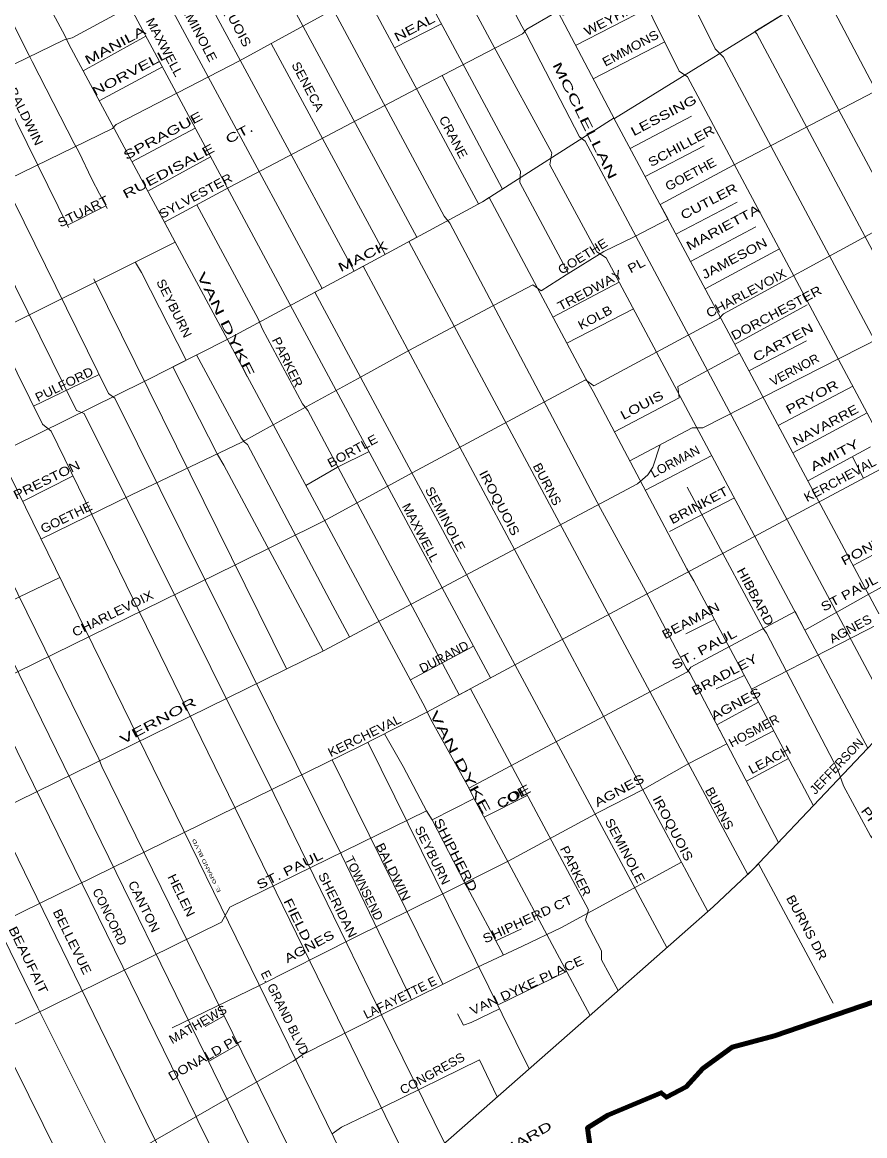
# Model space of a CAD drawing. Extents: x 34705 to 138605, y 34275 to 143551.
# Drawn here: x 109243 to 116315, y 106218 to 115565 of the extents above; entities that cross this region are included whole.
import ezdxf
from ezdxf.enums import TextEntityAlignment as Align

# ---------------------------------------------------------------- set-up
doc = ezdxf.new("R2010")
doc.units = 0
doc.header["$LTSCALE"] = 30
for name, color, linetype, lineweight in [('1', 7, 'Continuous', 13), ('11', 7, 'Continuous', 13), ('3', 7, 'Continuous', 13), ('58', 7, 'Continuous', 106)]:
    doc.layers.add(name, color=color, linetype=linetype, lineweight=lineweight)

msp = doc.modelspace()

# ---------------------------------------------------------------- linework, layer by layer
at = {"layer": '1'}
for p, q in [((113886.78, 115371.05), (114496.41, 115682.06)), ((112367.5, 115350.01), (112760.69, 115552.45)), ((109752.78, 115158.44), (110281.24, 115447.03)), ((111331.39, 115387.68), (112288.76, 113616.18)), ((114035.18, 115090.07), (114636.51, 115399.94)), ((109888.37, 114906.05), (110419.43, 115189.78)), ((112768.64, 115118.2), (113273.77, 114165.05)), ((114345.6, 114506.33), (114860.25, 114775.18)), ((110163.35, 114394.23), (110694.85, 114677.04)), ((114471.31, 114271.08), (114967.12, 114527.61)), ((110295.53, 114148.19), (110823.89, 114435.94)), ((114729.93, 113787.1), (115242.73, 114054.99)), ((109622.03, 113861.42), (109944.08, 114024.34)), ((114853.32, 113556.17), (115400.22, 113846.81)), ((114976.35, 113325.95), (115599.28, 113662.78)), ((109844, 113412.08), (111462.04, 110136.55)), ((113696.77, 113090.42), (114254.23, 113383.62)), ((113814.34, 112869.61), (114374.34, 113158.54)), ((115227.64, 112861.31), (115832.85, 113193.12)), ((109337.82, 112341.44), (109888.87, 112607.97)), ((115588.54, 112180.29), (116213.95, 112510.8)), ((115716.46, 111953.21), (116334.36, 112285.15)), ((115836.78, 111715.73), (116362.4, 111999.78)), ((114473.5, 111636.06), (115031.56, 111927.06)), ((116211.01, 111917.96), (116305.48, 111736.85)), ((109244.17, 111542.82), (109669.91, 111756.41)), ((114674.81, 111289.59), (115221.21, 111571.7)), ((114813.85, 110430.13), (115052.58, 110552.45)), ((112500.57, 110043.86), (113031.45, 110327.09)), ((115066.96, 109968.76), (115303.94, 110081.36)), ((115550.43, 109617.74), (115314.93, 109493.76)), ((112144.23, 109520.93), (113497.34, 106777.82)), ((111843.37, 109372.24), (112774.54, 107490.01)), ((115673.8, 109385.27), (115321.55, 109194.16)), ((113482.27, 109074.12), (113119.43, 108892.64)), ((113119.43, 108892.64), (113482.27, 109074.12)), ((113232.85, 107314), (113812.1, 107597.42)), ((110777.33, 107133.27), (110936.56, 107225.16)), ((110806.19, 106842.08), (111055.76, 106982.12))]:
    msp.add_line(p, q, dxfattribs=at)
for points in [[(109066.8, 125332.04), (109139.19, 124140.51), (109193.78, 124144.98), (109227.01, 123732.2), (109292.24, 123739.86), (109299.93, 123624.73), (109369.7, 123008.18), (109372.73, 122982.47), (109448.74, 123000.85), (109451.11, 122990.73), (109683.7, 122092.08), (109694.5, 122052.82), (109774.89, 122075.33), (109805.8, 122057.18), (110288.42, 121714), (110509.38, 121562.77), (110526.82, 121556.95), (110678.01, 121446.44), (110741.97, 121388.27), (113721.98, 115682.24), (113768.5, 115595), (114188.6, 114799.58), (114229.3, 114723.97), (116785.76, 109939.79)], [(111500.38, 122480.84), (111640.33, 122189.5), (111675.22, 122113.89), (112175.28, 121094.54), (112529.97, 120408.19), (113442.88, 118562.88), (113512.65, 118464), (115060.8, 115340.52), (115130.58, 115270.73), (117546.31, 110742.66)], [(112519.78, 121943.18), (112884.67, 121200.69), (112919.56, 121125.07), (112977.7, 121037.82), (114059.23, 118836.26), (114117.38, 118766.46), (115636.45, 115689.52), (118019.39, 111239.65)], [(112894.44, 121929.17), (113280.07, 121136.71), (113303.32, 121037.82), (114332.52, 119016.58), (114384.85, 118935.14), (115124.76, 117466.47), (115153.84, 117385.04), (115915.56, 115866.92), (115979.52, 115808.75), (118244.33, 111511.78), (118360.62, 111453.62), (119805.57, 108692.21)], [(111459.91, 121748.93), (111797.32, 121059.65), (112227.61, 120210.43), (113134.7, 118388.39), (113204.48, 118283.69), (114758.44, 115154.39), (114828.22, 115107.86), (117297.53, 110480.03)], [(110220.41, 121405.67), (110538.45, 121186.15), (110573.34, 121023.29), (112931.19, 116490.75), (113437.06, 115531.01), (113471.95, 115467.03), (113921.13, 114601.82), (113967.64, 114566.92), (116562.83, 109704.45)], [(109880.95, 121237.35), (110269.12, 120515), (110349.58, 120678.23), (110381.46, 120617.59), (110962.92, 119529.89), (113187.03, 115385.6), (113688.54, 114468.04), (113671.1, 114369.16), (114066.49, 113636.27), (114145, 113588.3), (116342.08, 109471.41)], [(109617.34, 121115.33), (110079.09, 120251.14), (110111.31, 120194.86), (110187.4, 120349.23), (110212.83, 120303.49), (110387.27, 119995.22), (110410.53, 119931.23), (113425.43, 114313.91), (113419.62, 114220.84), (113828.05, 113455.31)], [(108696.71, 120932.51), (109619.74, 119212.88), (109852.32, 118773.74), (110294.24, 117965.24), (110340.75, 117866.35), (112554.87, 113760.08), (112487.03, 113723.4), (115332.38, 108411.13), (115378.66, 108454.42), (115422.3, 108500.45), (116051.29, 107331.62)], [(109360.57, 120944.61), (109904.65, 119931.23), (109983.15, 119784.36), (110224.46, 119335.03), (110355.29, 119092.19), (113072.15, 114039.77), (113105.05, 114057.56), (113162.65, 114094.26), (113970.56, 112576.21), (114034.52, 112465.7), (114822.4, 110976.66), (114880.55, 110874.88), (115386.42, 109926.78), (115884.46, 108988.32)], [(109100.82, 120788.27), (110073.28, 118983.13), (110134.33, 118876.98), (112785.82, 113935.83), (112832.34, 113877.67), (113605.69, 112417.71), (113640.58, 112347.91), (114095.57, 111482.7), (114473.52, 110790.53), (114816.59, 110141.99), (114845.66, 110101.28), (115591.68, 108679.26)], [(108335.91, 120346.63), (109765.1, 117680.22), (109811.62, 117598.79), (110250.62, 116775.76), (110680.91, 115973.07), (112028.99, 113475.73), (112104.34, 113516.47), (114998.27, 108098.61)], [(108087.07, 120178.1), (110041.33, 116523.61), (111759.47, 113330.67), (111699.72, 113298.51), (114653.95, 107796.92)], [(107093.68, 120071.85), (107271.88, 119733.17), (107451.38, 119386.86), (107483.44, 119386.86), (108611.78, 117283.36), (109600.68, 115452.42), (109632.74, 115381.87), (112625.09, 109812.1), (112669.97, 109715.9), (112990.52, 109138.72), (113028.98, 109061.76), (114009.65, 107228.03)], [(107824.55, 120035.9), (108933.6, 117971.05), (109003.38, 117825.64), (110151.77, 115688.06), (113174.43, 110060.91)], [(105452.74, 119529.55), (105596.99, 119231.34), (107558.77, 115242.39), (107610.06, 114960.22), (109071.78, 111984.52), (109078.19, 111881.91), (112490.46, 104910.87), (112500.77, 104893)], [(106487.07, 119496.74), (107193.34, 118060.95), (107225.4, 118016.06), (109967.72, 112447.88), (110019.01, 112409.4), (111921.48, 108574.36), (112510.11, 107358.72)], [(114214.54, 114757.65), (115917.23, 115811.2), (115987.06, 115857.77), (116970.52, 116474.81), (117546.63, 116824.08), (118407.89, 117353.81), (118460.26, 117371.27), (119769.6, 118657.75), (120920.37, 119251.51), (121120.04, 119348.3)], [(115393.11, 115486.9), (115917.23, 115811.2), (115987.06, 115857.77), (116970.52, 116474.81), (117546.63, 116824.08), (118407.89, 117353.81), (118964.57, 117832.25), (119838.66, 118496.53)], [(107502.96, 118190.33), (107879.32, 117406.82), (108174.23, 116823.22), (108719.17, 115707.34), (108764.05, 115598.31), (109632.03, 113841.19)], [(106930.17, 117914.26), (109698.45, 112306.79), (109762.56, 112281.14), (111357.31, 109081), (111966.36, 107830.44), (112261.27, 107227.61), (112786.97, 106156.61)], [(98591.48, 110019.15), (101972.73, 111675.24), (103913.46, 112629.92), (104399.38, 112868.59), (107744.02, 114513.07), (108442.33, 114856.52), (109593.1, 115416.81), (109662.93, 115434.27), (111475.65, 116416.6), (113895.62, 117691.33), (113960.58, 117560.28), (114431.85, 117790.4)], [(106941.51, 113161.42), (108186.29, 113781.05), (108250.3, 113843.63), (108808.95, 114093.94), (110000.45, 114671.7), (110029.55, 114706.63), (111065.38, 115242.18), (112765.01, 116171.96), (112671.78, 116345.48), (113215.62, 116620.34), (113267.99, 116649.45), (113413.47, 116730.94), (113861.43, 116960.74)], [(108471.24, 116859.6), (108544.47, 116786.35), (109300.97, 115285.68), (109326.61, 115234.37), (109679.22, 114548.17), (109717.69, 114477.62), (109826.67, 114246.75), (109890.78, 114124.9), (109948.48, 114015.88), (109956.3, 114000.84)], [(105797.18, 111399.32), (105881.84, 111371.09), (106397.49, 111617.75), (106373.8, 111666.25), (108599.46, 112744.89), (108756.58, 112838.02), (110526.23, 113718.79), (110435.99, 113886.75), (110981.01, 114179.81), (112552.22, 115006.41), (113442.57, 115466.29), (113477.48, 115507.04), (113710.26, 115640.92), (113785.91, 115623.46), (114362.02, 115915.98), (115147.62, 116317.64)], [(109398.88, 111226.76), (110159.03, 111598.11), (111085.75, 112040.52), (111347.62, 112186.05), (112086.67, 112587.71), (112488.2, 112808.92), (113198.16, 113187.29), (113529.86, 113361.93), (113599.69, 113309.54), (113809.18, 113443.43), (114123.43, 113641.35), (114379.48, 113763.59), (114663.89, 113910.67), (114597.23, 114035.41), (115213.09, 114364.63), (116394.41, 114981.68), (116417.69, 115057.35), (118934.23, 116289.87)], [(103390.08, 100620.34), (111287.98, 105212.28), (112213.24, 105742.01), (112517.3, 105916.64), (114001.22, 107220.59), (115042.88, 108140.33), (115378.94, 108454.67), (118009.27, 111231.38), (118294.41, 111464.23), (120540.66, 112907.88), (120691.96, 113012.66), (122079.87, 113725.76), (123691.81, 114016.82), (124355.21, 114109.95), (126298.86, 114360.26), (126409.42, 114383.55), (128980.68, 115821.76)], [(104051.67, 107444.7), (104825.64, 107904.58), (104918.75, 107939.5), (105320.28, 108183.99), (105966.22, 108521.62), (106827.48, 108934.92), (106920.59, 108993.14), (111031.93, 111010.18), (111770.98, 111376.91), (112521.67, 111784.39), (113970.67, 112564.43), (114040.5, 112512.04), (115093.8, 113076.69), (115128.71, 113117.44), (116414.78, 113815.98), (116887.6, 114070.66), (116969.07, 114143.43), (117091.27, 114347.17), (117143.65, 114399.56), (119333.43, 115468.66)], [(115393.11, 115486.9), (115409.68, 115468.49), (117792.87, 111002.94)], [(107047.11, 115150.16), (109204.8, 110766.04), (109884.37, 109380.81), (109910.02, 109316.68), (110621.64, 107867.31), (111784.35, 105496.46)], [(108027.16, 114992.93), (109412.77, 112189.81), (109485.89, 112133.55), (112518.61, 105917.79)], [(106525.24, 114896.44), (107151.66, 113620.34), (110698.58, 106384.29), (110724.22, 106326.57), (111285.17, 105210.68)], [(99622.96, 107156.95), (99848.68, 107262.79), (100188.92, 107440.65), (100537.2, 107693.33), (100968.9, 107962.79), (103779.62, 109348.23), (104572.5, 109741.16), (105072.96, 109985.65), (105247.54, 110090.43), (106097.16, 110492.09), (110265.23, 112549.88), (110957.73, 112899.15), (112028.48, 113475.45), (113105.05, 114057.56), (114210.72, 114761.93)], [(105838, 114523.9), (109374.69, 107291.74), (109999.77, 106037.98), (110044.65, 105954.61), (110041.44, 105944.98), (110594.62, 104809.15)], [(114343.05, 111882.6), (114865.88, 112158.86), (114955.87, 112158.86), (116447.81, 112918.44), (117240.89, 113357.3), (119758.65, 114593.9)], [(105410.48, 114313.93), (105596.68, 113932.88), (105674.36, 113970.97), (109022.08, 107118.58), (109054.14, 107041.62), (110256.75, 104612.72), (110148.21, 104549.61), (110451.51, 103928.7)], [(110707.6, 114032.54), (111221.67, 113074.98), (111259.47, 112987.73), (111593.81, 112362.46), (111640.33, 112304.29), (112909.12, 109918.59), (113004.15, 109969.57), (113995.27, 108113.47), (113972.01, 108026.22), (114104.29, 107768.84), (114105.75, 107694.68), (114246.28, 107436.96)], [(107372.9, 113850.14), (108025.17, 112524.83), (111534.66, 105353.51)], [(108341.95, 107654.27), (112091.04, 109493.76), (112638.05, 109773.17), (114482.77, 110762.77), (119517.92, 113453.62), (120145.08, 113798.95)], [(110190.92, 113549.98), (110192.1, 113547.72), (110243.39, 113464.35), (110619.43, 112728.53), (110505.55, 112671.09), (110882.89, 111936.43), (110934.18, 111846.65), (111767.98, 110286.75)], [(106799.91, 113452.41), (106840.73, 113369.76), (107129.23, 112773.34), (107417.73, 112183.33), (107469.02, 112106.37), (109733.71, 107458.48), (110333.15, 106230.37), (110944.91, 105012.82)], [(115343.18, 112639.45), (115827.03, 112890.42), (115827.03, 112890.42)], [(110704.94, 112771.65), (111081.63, 112077.52), (111107.28, 112039.04), (111132.92, 112019.8), (111850.96, 110666.63), (111990.7, 110405.28)], [(114213.68, 112127.1), (114756.28, 112413.08), (114744.64, 112506.22), (115262.56, 112785.63)], [(101237.33, 105303.94), (101290.09, 105195.91), (101674.44, 105382.43), (101630.74, 105471.24), (103126.41, 106197.51), (103295.16, 106220.8), (103632.68, 106232.44), (104325.18, 106610.82), (106206.27, 107700.84), (106252.83, 107747.41), (108394.33, 108777.75), (108976.26, 108940.75), (109040.27, 108946.57), (111770.98, 110288.35), (114407.12, 111691.25), (114494.41, 111766.93), (114535.14, 111830.96), (114597.08, 112016.83)], [(111623, 111677.33), (111888.82, 111830.96), (112154.04, 111960.53)], [(114825.31, 111663.01), (115462.01, 110476.44), (115491.09, 110435.72), (116090, 109288.41), (116136.52, 109154.63), (116363.29, 108735.84), (116485.4, 108578.79)], [(108694.04, 106916.51), (110914.08, 108009.36), (110983.91, 108137.42), (112635.16, 108945.15), (112682.5, 108869.82), (113035.66, 109049.25), (112992.31, 109135.14), (114826.11, 110110.8), (114855.2, 110151.55), (115729.79, 110618.71), (115812.95, 110462.89), (116350.76, 110762.77), (116705.74, 110960.69), (117271.04, 111258.63)], [(116216.95, 111004.26), (116595.88, 111206.42), (117091.34, 110262.37)], [(104252.68, 108222.73), (105727.63, 109028.06), (106588.89, 109441.37), (107277.02, 109796.46), (108400.15, 110349.47), (109556.71, 110904.33)], [(110500.91, 107124.54), (111234.14, 107479.63), (112019.75, 107875.47), (112773.35, 108248.03), (113320.36, 108521.62), (114082.69, 108934.92), (114449.31, 109121.2), (114839.2, 109342.41), (115156.84, 109508.12), (115072.93, 109668.06), (115422.8, 109858.21), (115365.22, 109966.5), (116847.93, 110726.16)], [(112283.76, 109592.2), (112439.17, 109318.28), (112637.91, 108939.91), (112682.79, 108869.37), (112958.46, 108337.08), (112977.7, 108305.01), (113281.61, 107734.21)], [(102325.17, 101481.39), (105929.85, 103550.33), (107652.36, 104557.4), (108228.47, 104906.67), (108485.98, 105087.12), (108695.48, 105203.55), (108806.04, 105290.86), (110963.55, 106527.87), (111516.38, 106842.21), (111597.85, 106900.42), (112267.07, 107238.05), (113064.31, 107633.89), (113442.57, 107808.52), (113768.45, 107965.7), (114776.41, 108513.55)], [(112896.51, 107240.42), (112947.93, 107144.91), (113011.94, 107168.2), (113247.96, 107283.37)], [(111842.96, 106233.92), (111923.73, 106289.2), (112272.89, 106458.01), (113081.77, 106853.85), (113230.61, 106543.44)], [(111843.24, 106234.11), (111923.73, 106289.2), (112272.89, 106458.01), (113081.77, 106853.85), (113230.61, 106543.44)], [(114674.16, 106552.89), (114650.09, 106540.23), (114616.32, 106569.86)]]:
    msp.add_lwpolyline(points, dxfattribs=at)
at = {"layer": '11'}
msp.add_lwpolyline([(113217.49, 107854.63), (113381.69, 107930.43), (113433.74, 107955.54)], dxfattribs=at)
at = {"layer": '58'}
msp.add_lwpolyline([(129983.33, 109077.63), (127080.95, 108699.07), (124477.41, 108360.94), (124230.15, 108410), (123736.65, 108436.74), (123511.33, 108403.87), (121737.61, 108588.9), (119778.1, 108646.11), (118825.14, 108253.65), (117226.65, 107626.21), (115557.68, 107055.75), (115201.53, 106961.21), (114956.09, 106780.76), (114815.32, 106627.15), (114650.09, 106540.23), (114607, 106578.04), (114157.64, 106389.2), (113987.66, 106282.88), (114010.89, 106120.17)], dxfattribs=at)

# ---------------------------------------------------------------- texts
at = {"layer": '11'}
for s, rotation, width, p in [('IROQUOIS', 297.782, 1.2, (110962.2, 115615.25)), ('SEMINOLE', 297.783, 1.15, (110676.94, 115485.97)), ('WEYHER ', 27.152, 1.2, (114233.87, 115576.67)), ('MAXWELL', 297.782, 1.1, (110403.47, 115338.27)), ('NEAL ', 27.783, 1.4, (112569.51, 115494.29)), ('MANILA      ', 28.027, 1.5, (110150.55, 115397.92)), ('EMMONS ', 28.306, 1.15, (114379.96, 115321.47)), ('NORVELL      ', 28.027, 1.5, (110274.61, 115167.15)), ('SENECA', 297.783, 1.1, (111606.12, 115008.03)), ('MCCLELLAN', 296.401, 1.8, (113931.74, 114723)), ('BALDWIN', 296.238, 1.15, (109237.84, 114757.05)), ('LESSING ', 27.887, 1.4, (114661.76, 114758.64)), ('SPRAGUE     ', 28.211, 1.5, (110532.32, 114629.44)), ('RUEDISALE   CT.   ', 28.07, 1.5, (110705.12, 114398.27)), ('CRANE', 297.784, 1.1, (112828.12, 114583.5)), ('SCHILLER', 28.178, 1.25, (114792.23, 114493.31)), ('GOETHE', 28.061, 1.1, (114870.99, 114256.42)), ('SYLVESTER', 28.099, 1.15, (110714.92, 114074.23)), ('CUTLER ', 28.048, 1.3, (115040.18, 114036.25)), ('STUART', 26.217, 1.15, (109770.01, 113943.21)), ('MARIETTA ', 28.232, 1.35, (115159.91, 113817.55)), ('MACK', 26.141, 1.55, (112118.09, 113565.12)), ('GOETHE', 31.899, 1.1, (113967.13, 113568.05)), ('JAMESON ', 28.113, 1.25, (115253.34, 113557.44)), ('TREDWAY  PL', 28.1, 1.2, (114120.05, 113332.81)), ('VAN DYKE', 296.238, 1.9, (110917.59, 113012.82)), ('CHARLEVOIX', 28.097, 1.15, (115337.01, 113257.25)), ('SEYBURN', 296.239, 1.1, (110484.04, 113147.06)), ('DORCHESTER ', 28.195, 1.2, (115605.19, 113100.05)), ('KOLB', 28.101, 1.15, (114068.59, 113053.18)), ('CARTEN  ', 28.195, 1.35, (115680.69, 112861.25)), ('PARKER', 295.998, 1.1, (111435.38, 112695.36)), ('VERNOR', 28.101, 1.05, (115743, 112614.52)), ('PULFORD', 26.147, 1.1, (109611.2, 112491.43)), ('PRYOR  ', 28.196, 1.35, (115923.08, 112403.1)), ('LOUIS', 28.098, 1.3, (114461.98, 112316.85)), ('NAVARRE ', 28.196, 1.25, (116018.02, 112158.42)), ('BORTLE', 28.447, 1.15, (112032.69, 111933.08)), ('LORMAN', 28.102, 1.05, (114740.35, 111844.3)), ('AMITY ', 28.196, 1.45, (116097.43, 111907.67)), ('KERCHEVAL', 28.197, 1.1, (116124.9, 111693.49)), ('PRESTON ', 25.997, 1.25, (109479.45, 111696.69)), ('IROQUOIS', 297.782, 1.2, (113215.34, 111512.61)), ('BURNS', 297.785, 1.1, (113616.03, 111669.45)), ('SEMINOLE', 297.783, 1.15, (112760.27, 111378.14)), ('BRINKET', 28.099, 1.25, (114938.72, 111476.99)), ('GOETHE', 25.996, 1.1, (109628.86, 111374.96)), ('MAXWELL', 297.782, 1.1, (112553.04, 111264.26)), ('PONTIAC ', 28.197, 1.35, (116423.16, 111154.4)), ('HIBBARD', 298.194, 1.2, (115364.23, 110725.67)), ('ST PAUL', 28.196, 1.25, (116202.09, 110739.84)), ('CHARLEVOIX', 26.081, 1.15, (110017.82, 110567.45)), ('BEAMAN ', 28.099, 1.25, (114887.22, 110516.77)), ('AGNES', 28.194, 1.1, (116212.72, 110439.23)), ('ST. PAUL', 28.254, 1.35, (114984.46, 110269.62)), ('DURAND', 27.714, 1.05, (112799.87, 110204.77)), ('BRADLEY ', 28.252, 1.3, (115171.14, 110063.79)), ('AGNES ', 28.26, 1.3, (115266.61, 109816.72)), ('VERNOR', 28.101, 1.65, (110399.41, 109668.57)), ('KERCHEVAL', 26.142, 1.1, (112132.46, 109541.35)), ('VAN DYKE', 298.209, 1.9, (112885.7, 109336.21)), ('HOSMER', 28.258, 1.05, (115402.09, 109583.94)), ('LEACH', 28.252, 1.15, (115534.38, 109341.76)), ('AGNES ', 28.26, 1.3, (114287.2, 109091.2)), ('COE ', 28.26, 1.4, (113401.94, 109042.61)), ('COE ', 28.26, 1.3, (113391.97, 109037.25)), ('BURNS', 297.785, 1.1, (115061.85, 108947.96)), ('IROQUOIS', 297.782, 1.2, (114671.4, 108781.21)), ('PRIVATE', 307.224, 1.3, (116447.3, 108721.42)), ('SEYBURN', 296.239, 1.1, (112652.88, 108555.58)), ('SHIPHERD ', 297.006, 1.3, (112856.13, 108543.26)), ('SEMINOLE', 297.783, 1.15, (114269.55, 108593.72)), ('BALDWIN', 296.239, 1.15, (112323.25, 108416.64)), ('PARKER', 295.998, 1.1, (113853.98, 108424.06)), ('ST. PAUL', 26.142, 1.35, (111503.51, 108415.57)), ('CANTON', 296.061, 1.1, (110231.15, 108125.66)), ('HELEN', 296.055, 1.15, (110544.38, 108219.37)), ('SHERIDAN', 296.24, 1.15, (111856.09, 108138.85)), ('BURNS DR', 298.23, 1.15, (115795.35, 107947.74)), ('FIELD', 296.236, 1.35, (111517.87, 108014.97)), ('SHIPHERD CT', 24.645, 1.2, (113499.69, 108001.17)), ('BELLEVUE', 296.059, 1.15, (109627.97, 107830.31)), ('BEAUFAIT', 296.059, 1.25, (109259.93, 107676.63)), ('AGNES ', 28.26, 1.3, (111685.54, 107781.33)), ('VAN DYKE PLACE', 24.82, 1.2, (113493, 107444.73)), ('MATHEWS', 29.949, 1.05, (110734.69, 107119.91)), ('DONALD PL', 29.612, 1.2, (110791.88, 106843.4)), ('CONGRESS', 29.099, 1.05, (112702.56, 106707.82)), ('GABRIEL RICHARD', 29.665, 1.6, (113059.64, 105914.12))]:
    msp.add_text(s, height=75, rotation=rotation, dxfattribs=dict(at, width=width)).set_placement(p, align=Align.CENTER)
for s, rotation, p in [('JEFFERSON', 46.537, (116105.2, 109293.52)), ('TOWNSEND', 296.239, (112078.99, 108278.59)), ('CONCORD', 296.056, (109943.57, 108038.9)), ('E. GRAND BLVD.   ', 296.238, (111437.73, 107185.22)), ('LAFAYETTE E', 26.262, (112431.02, 107343.6))]:
    msp.add_text(s, height=75, rotation=rotation, dxfattribs=at).set_placement(p, align=Align.CENTER)
at = {"layer": '3', "width": 1.6}
msp.add_text('E. GRAND BLVD', height=30, rotation=116.06, dxfattribs=at).set_placement((110801.63, 108490.94), align=Align.CENTER)

doc.saveas('drawing.dxf')
